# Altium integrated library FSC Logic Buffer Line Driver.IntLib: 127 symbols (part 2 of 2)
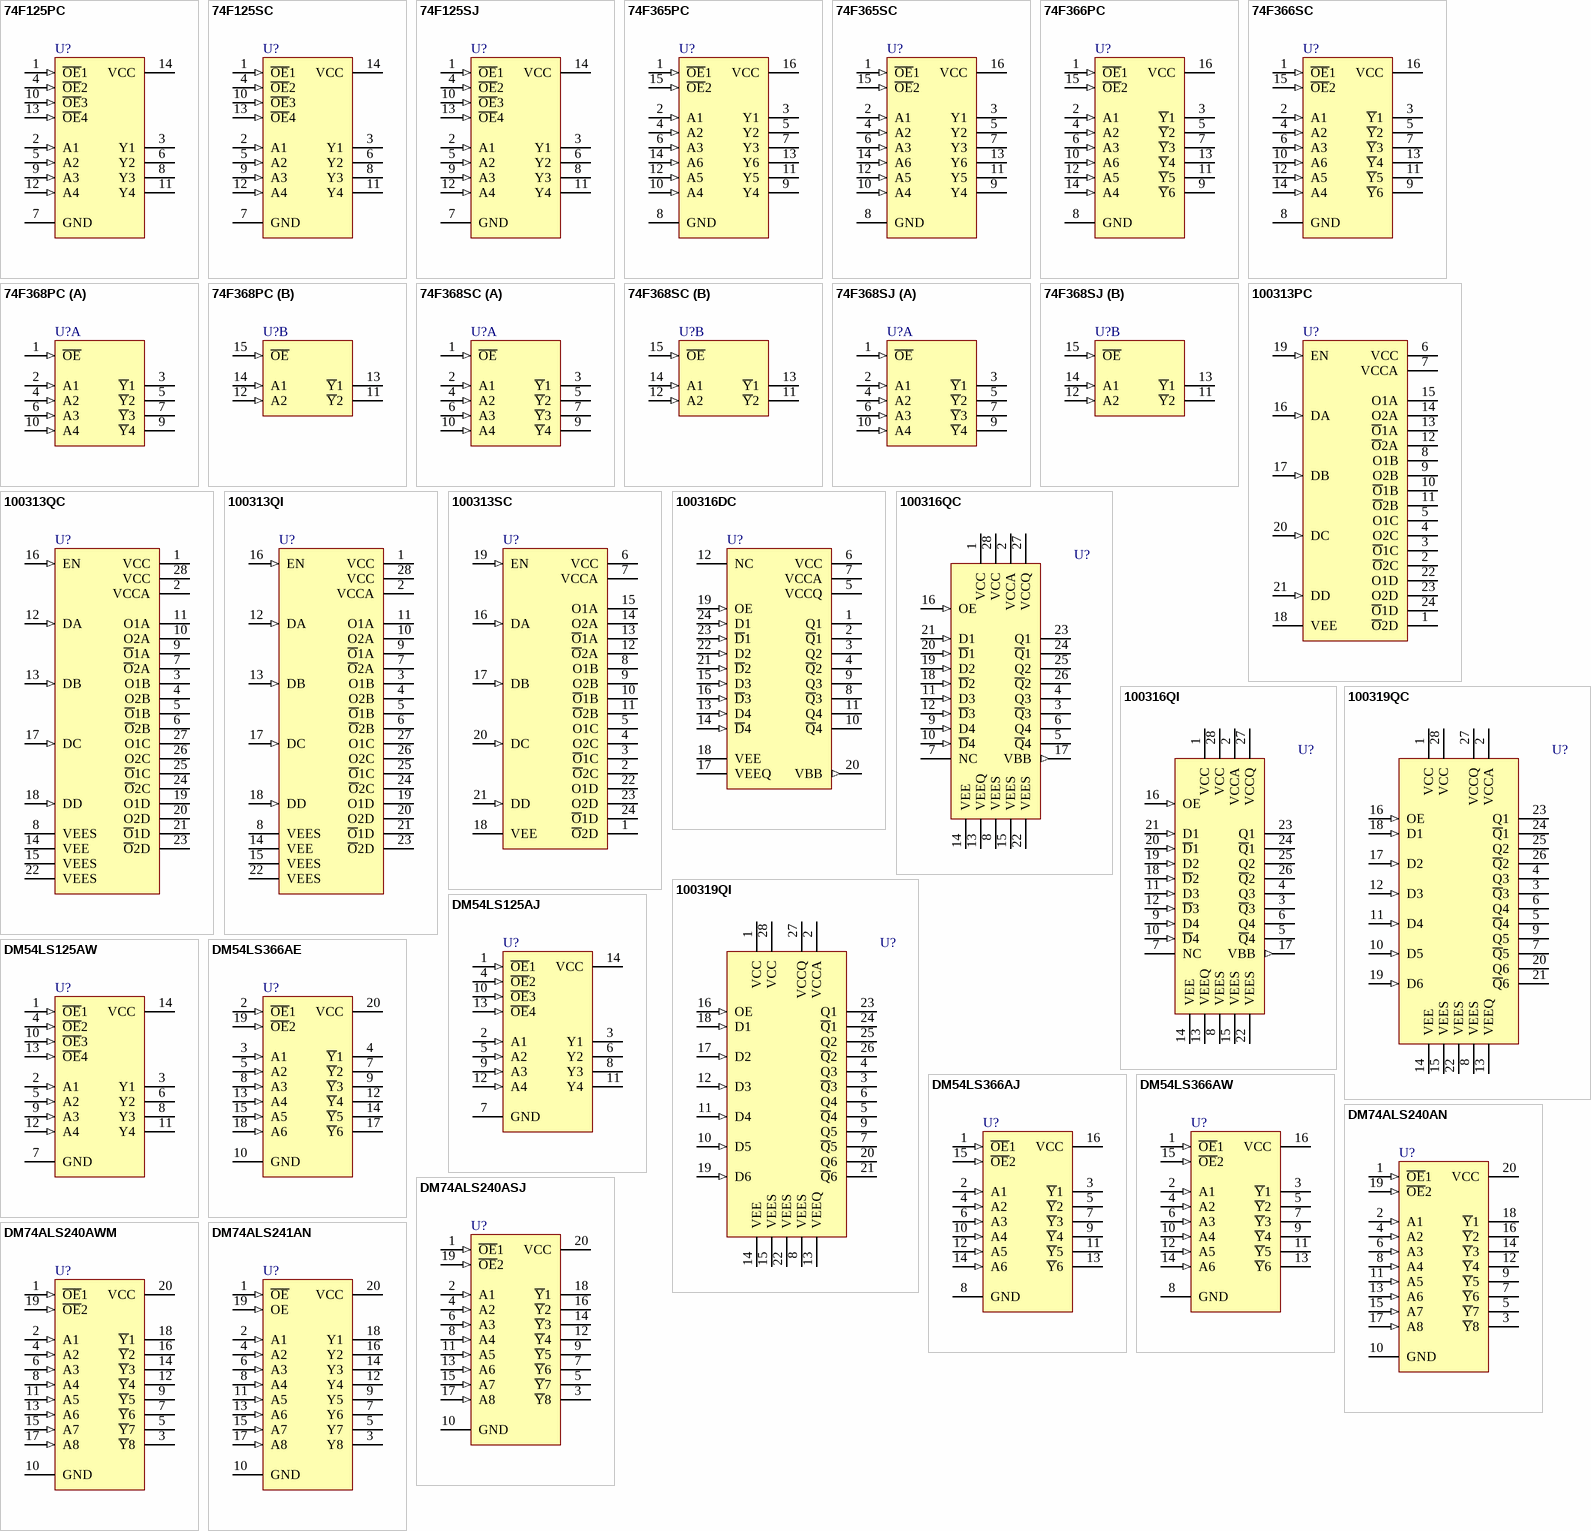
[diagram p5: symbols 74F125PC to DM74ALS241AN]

## 100313PC
designator U?
Low Power Quad Driver; Note: All inputs have 50k Ohm pull-down resistors. VCC = VCCA = GND.
footprint N24E (DIP, 24-Leads, Row Spacing 10.16mm, Pitch 2.54mm, Body 30.59x8.69mm)
3D model 6Y (DIP, 24-Pin, Row Spacing 10.16 mm, Pitch 2.54 mm)
pins: 1 ~{O}2D (oe), 2 ~{O}2C (oe), 3 ~{O}1C (oe), 4 O2C (oe), 5 O1C (oe), 6 VCC (power), 7 VCCA (power), 8 O1B (oe), 9 O2B (oe), 10 ~{O}1B (oe), 11 ~{O}2B (oe), 12 ~{O}2A (oe), 13 ~{O}1A (oe), 14 O2A (oe), 15 O1A (oe), 16 DA (in), 17 DB (in), 18 VEE (power), 19 EN (in), 20 DC (in), 21 DD (in), 22 O1D (oe), 23 O2D (oe), 24 ~{O}1D (oe)

## 100313QC
designator U?
Low Power Quad Driver; Note: All inputs have 50k Ohm pull-down resistors. VCC = VCCA = GND.
footprint V28A_N (Leaded Chip Carrier, 28-Leads, Body 11.5x11.5mm, Pitch 1.27mm, IPC Medium Density)
footprint V28A_L (Leaded Chip Carrier, 28-Leads, Body 11.5x11.5mm, Pitch 1.27mm, IPC High Density)
footprint V28A_M (Leaded Chip Carrier, 28-Leads, Body 11.5x11.5mm, Pitch 1.27mm, IPC Low Density)
3D model 100313-V28A (28-Pin Leaded Chip Carrier 1.27 mm Pitch)
pins: 1 VCC (power), 2 VCCA (power), 3 O1B (oe), 4 O2B (oe), 5 ~{O}1B (oe), 6 ~{O}2B (oe), 7 ~{O}2A (oe), 8 VEES (power), 9 ~{O}1A (oe), 10 O2A (oe), 11 O1A (oe), 12 DA (in), 13 DB (in), 14 VEE (power), 15 VEES (power), 16 EN (in), 17 DC (in), 18 DD (in), 19 O1D (oe), 20 O2D (oe), 21 ~{O}1D (oe), 22 VEES (power), 23 ~{O}2D (oe), 24 ~{O}2C (oe), 25 ~{O}1C (oe), 26 O2C (oe), 27 O1C (oe), 28 VCC (power)

## 100313QI
designator U?
Low Power Quad Driver; Note: All inputs have 50k Ohm pull-down resistors. VCC = VCCA = GND.
footprint V28A_N (Leaded Chip Carrier, 28-Leads, Body 11.5x11.5mm, Pitch 1.27mm, IPC Medium Density)
footprint V28A_L (Leaded Chip Carrier, 28-Leads, Body 11.5x11.5mm, Pitch 1.27mm, IPC High Density)
footprint V28A_M (Leaded Chip Carrier, 28-Leads, Body 11.5x11.5mm, Pitch 1.27mm, IPC Low Density)
3D model 100313-V28A (28-Pin Leaded Chip Carrier 1.27 mm Pitch)
pins: 1 VCC (power), 2 VCCA (power), 3 O1B (oe), 4 O2B (oe), 5 ~{O}1B (oe), 6 ~{O}2B (oe), 7 ~{O}2A (oe), 8 VEES (power), 9 ~{O}1A (oe), 10 O2A (oe), 11 O1A (oe), 12 DA (in), 13 DB (in), 14 VEE (power), 15 VEES (power), 16 EN (in), 17 DC (in), 18 DD (in), 19 O1D (oe), 20 O2D (oe), 21 ~{O}1D (oe), 22 VEES (power), 23 ~{O}2D (oe), 24 ~{O}2C (oe), 25 ~{O}1C (oe), 26 O2C (oe), 27 O1C (oe), 28 VCC (power)

## 100313SC
designator U?
Low Power Quad Driver; Note: All inputs have 50k Ohm pull-down resistors. VCC = VCCA = GND.
footprint M24B_N (SOIC, 24-Leads, Body 15.4x7.5mm, Pitch 1.27mm, IPC Medium Density)
footprint M24B_L (SOIC, 24-Leads, Body 15.4x7.5mm, Pitch 1.27mm, IPC High Density)
footprint M24B_M (SOIC, 24-Leads, Body 15.4x7.5mm, Pitch 1.27mm, IPC Low Density)
3D model M24B (24-Pin Small Outline Integrated Circuit 1.27 mm Pitch)
pins: 1 ~{O}2D (oe), 2 ~{O}2C (oe), 3 ~{O}1C (oe), 4 O2C (oe), 5 O1C (oe), 6 VCC (power), 7 VCCA (power), 8 O1B (oe), 9 O2B (oe), 10 ~{O}1B (oe), 11 ~{O}2B (oe), 12 ~{O}2A (oe), 13 ~{O}1A (oe), 14 O2A (oe), 15 O1A (oe), 16 DA (in), 17 DB (in), 18 VEE (power), 19 EN (in), 20 DC (in), 21 DD (in), 22 O1D (oe), 23 O2D (oe), 24 ~{O}1D (oe)

## 100316DC
designator U?
Low Power Quad Differential Line Driver with Cut-Off; Note: VCC = VCCA = GND.
footprint J24E (DIP, 24-Leads, Row Spacing 10.16mm, Pitch 2.54mm, Body 30.48x9.14mm)
3D model 6Y (DIP, 24-Pin, Row Spacing 10.16 mm, Pitch 2.54 mm)
pins: 1 Q1 (hiz), 2 ~{Q}1 (hiz), 3 Q2 (hiz), 4 ~{Q}2 (hiz), 5 VCCQ (power), 6 VCC (power), 7 VCCA (power), 8 ~{Q}3 (hiz), 9 Q3 (hiz), 10 ~{Q}4 (hiz), 11 Q4 (hiz), 12 NC, 13 D4 (in), 14 ~{D}4 (in), 15 D3 (in), 16 ~{D}3 (in), 17 VEEQ (power), 18 VEE (power), 19 OE (in), 20 VBB (out), 21 ~{D}2 (in), 22 D2 (in), 23 ~{D}1 (in), 24 D1 (in)

## 100316QC
designator U?
Low Power Quad Differential Line Driver with Cut-Off; Note: VCC = VCCA = GND.
footprint V28A_N (Leaded Chip Carrier, 28-Leads, Body 11.5x11.5mm, Pitch 1.27mm, IPC Medium Density)
footprint V28A_L (Leaded Chip Carrier, 28-Leads, Body 11.5x11.5mm, Pitch 1.27mm, IPC High Density)
footprint V28A_M (Leaded Chip Carrier, 28-Leads, Body 11.5x11.5mm, Pitch 1.27mm, IPC Low Density)
3D model 100316-V28A (28-Pin Leaded Chip Carrier 1.27 mm Pitch)
pins: 1 VCC (power), 2 VCCA (power), 3 ~{Q}3 (hiz), 4 Q3 (hiz), 5 ~{Q}4 (hiz), 6 Q4 (hiz), 7 NC, 8 VEES (power), 9 D4 (in), 10 ~{D}4 (in), 11 D3 (in), 12 ~{D}3 (in), 13 VEEQ (power), 14 VEE (power), 15 VEES (power), 16 OE (in), 17 VBB (out), 18 ~{D}2 (in), 19 D2 (in), 20 ~{D}1 (in), 21 D1 (in), 22 VEES (power), 23 Q1 (hiz), 24 ~{Q}1 (hiz), 25 Q2 (hiz), 26 ~{Q}2 (hiz), 27 VCCQ (power), 28 VCC (power)

## 100316QI
designator U?
Low Power Quad Differential Line Driver with Cut-Off; Note: VCC = VCCA = GND.
footprint V28A_N (Leaded Chip Carrier, 28-Leads, Body 11.5x11.5mm, Pitch 1.27mm, IPC Medium Density)
footprint V28A_L (Leaded Chip Carrier, 28-Leads, Body 11.5x11.5mm, Pitch 1.27mm, IPC High Density)
footprint V28A_M (Leaded Chip Carrier, 28-Leads, Body 11.5x11.5mm, Pitch 1.27mm, IPC Low Density)
3D model 100316-V28A (28-Pin Leaded Chip Carrier 1.27 mm Pitch)
pins: 1 VCC (power), 2 VCCA (power), 3 ~{Q}3 (hiz), 4 Q3 (hiz), 5 ~{Q}4 (hiz), 6 Q4 (hiz), 7 NC, 8 VEES (power), 9 D4 (in), 10 ~{D}4 (in), 11 D3 (in), 12 ~{D}3 (in), 13 VEEQ (power), 14 VEE (power), 15 VEES (power), 16 OE (in), 17 VBB (out), 18 ~{D}2 (in), 19 D2 (in), 20 ~{D}1 (in), 21 D1 (in), 22 VEES (power), 23 Q1 (hiz), 24 ~{Q}1 (hiz), 25 Q2 (hiz), 26 ~{Q}2 (hiz), 27 VCCQ (power), 28 VCC (power)

## 100319QC
designator U?
Low Power Hex Line Driver with Cut-Off; Note: VCC = VCCA = GND.
footprint V28A_N (Leaded Chip Carrier, 28-Leads, Body 11.5x11.5mm, Pitch 1.27mm, IPC Medium Density)
footprint V28A_L (Leaded Chip Carrier, 28-Leads, Body 11.5x11.5mm, Pitch 1.27mm, IPC High Density)
footprint V28A_M (Leaded Chip Carrier, 28-Leads, Body 11.5x11.5mm, Pitch 1.27mm, IPC Low Density)
3D model 100319-V28A (28-Pin Leaded Chip Carrier 1.27 mm Pitch)
pins: 1 VCC (power), 2 VCCA (power), 3 ~{Q}3 (oe), 4 Q3 (oe), 5 ~{Q}4 (oe), 6 Q4 (oe), 7 ~{Q}5 (oe), 8 VEES (power), 9 Q5 (oe), 10 D5 (in), 11 D4 (in), 12 D3 (in), 13 VEEQ (power), 14 VEE (power), 15 VEES (power), 16 OE (in), 17 D2 (in), 18 D1 (in), 19 D6 (in), 20 Q6 (oe), 21 ~{Q}6 (oe), 22 VEES (power), 23 Q1 (hiz), 24 ~{Q}1 (hiz), 25 Q2 (hiz), 26 ~{Q}2 (hiz), 27 VCCQ (power), 28 VCC (power)

## 100319QI
designator U?
Low Power Hex Line Driver with Cut-Off; Note: VCC = VCCA = GND.
footprint V28A_N (Leaded Chip Carrier, 28-Leads, Body 11.5x11.5mm, Pitch 1.27mm, IPC Medium Density)
footprint V28A_L (Leaded Chip Carrier, 28-Leads, Body 11.5x11.5mm, Pitch 1.27mm, IPC High Density)
footprint V28A_M (Leaded Chip Carrier, 28-Leads, Body 11.5x11.5mm, Pitch 1.27mm, IPC Low Density)
3D model 100319-V28A (28-Pin Leaded Chip Carrier 1.27 mm Pitch)
pins: 1 VCC (power), 2 VCCA (power), 3 ~{Q}3 (oe), 4 Q3 (oe), 5 ~{Q}4 (oe), 6 Q4 (oe), 7 ~{Q}5 (oe), 8 VEES (power), 9 Q5 (oe), 10 D5 (in), 11 D4 (in), 12 D3 (in), 13 VEEQ (power), 14 VEE (power), 15 VEES (power), 16 OE (in), 17 D2 (in), 18 D1 (in), 19 D6 (in), 20 Q6 (oe), 21 ~{Q}6 (oe), 22 VEES (power), 23 Q1 (hiz), 24 ~{Q}1 (hiz), 25 Q2 (hiz), 26 ~{Q}2 (hiz), 27 VCCQ (power), 28 VCC (power)

## DM54LS125AJ
designator U?
Quad 3-State Buffer
footprint J14A (DIP, 14-Leads, Row Spacing 7.62mm, Pitch 2.54mm, Body 19.56x6.73mm)
3D model J14A (CerDIP, 14-Pin, Row Spacing 7.62 mm, Pitch 2.54 mm)
simulation model 74LS125 (SIMCODE)
signal-integrity model DM54LS125AJ
pins: 1 ~{OE}1 (in), 2 A1 (in), 3 Y1 (hiz), 4 ~{OE}2 (in), 5 A2 (in), 6 Y2 (hiz), 7 GND (power), 8 Y3 (hiz), 9 A3 (in), 10 ~{OE}3 (in), 11 Y4 (hiz), 12 A4 (in), 13 ~{OE}4 (in), 14 VCC (power)

## DM54LS125AW
designator U?
Quad 3-State Buffer
footprint W14B (DFP; 14 Leads; Body 9.8 x 7.1 mm (LxW max); Pitch 1.27 mm)
3D model W14B (DFP; 14 Leads; Body 9.8 x 7.1 mm (LxW max); Pitch 1.27 mm)
simulation model 74LS125 (SIMCODE)
signal-integrity model DM54LS125AW
pins: 1 ~{OE}1 (in), 2 A1 (in), 3 Y1 (hiz), 4 ~{OE}2 (in), 5 A2 (in), 6 Y2 (hiz), 7 GND (power), 8 Y3 (hiz), 9 A3 (in), 10 ~{OE}3 (in), 11 Y4 (hiz), 12 A4 (in), 13 ~{OE}4 (in), 14 VCC (power)

## DM54LS366AE
designator U?
Hex 3-State Inverting Buffer; Note: Pins 1, 6, 11 and 16 are not connected and not drawn.
footprint E20A (Leadless Chip Carrier; 20 Terminals; Body 8.9 x 8.9 mm)
footprint E20A_N (Leadless Chip Carrier, 20-Leads, Body 8.9x8.9mm, Pitch 1.27mm, IPC Medium Density)
footprint E20A_L (Leadless Chip Carrier, 20-Leads, Body 8.9x8.9mm, Pitch 1.27mm, IPC High Density)
footprint E20A_M (Leadless Chip Carrier, 20-Leads, Body 8.9x8.9mm, Pitch 1.27mm, IPC Low Density)
signal-integrity model DM54LS366AE
pins: 2 ~{OE}1 (in), 3 A1 (in), 4 ~{Y}1 (hiz), 5 A2 (in), 7 ~{Y}2 (hiz), 8 A3 (in), 9 ~{Y}3 (hiz), 10 GND (power), 12 ~{Y}4 (hiz), 13 A4 (in), 14 ~{Y}5 (hiz), 15 A5 (in), 17 ~{Y}6 (hiz), 18 A6 (in), 19 ~{OE}2 (in), 20 VCC (power)

## DM54LS366AJ
designator U?
Hex 3-State Inverting Buffer
footprint J16A (DIP, 16-Leads, Row Spacing 7.62mm, Pitch 2.54mm, Body 19.56x6.73mm)
3D model N16E (CerDIP, 16-Pin, Row Spacing 7.62 mm, Pitch 2.54 mm)
signal-integrity model DM54LS366AJ
pins: 1 ~{OE}1 (in), 2 A1 (in), 3 ~{Y}1 (hiz), 4 A2 (in), 5 ~{Y}2 (hiz), 6 A3 (in), 7 ~{Y}3 (hiz), 8 GND (power), 9 ~{Y}4 (hiz), 10 A4 (in), 11 ~{Y}5 (hiz), 12 A5 (in), 13 ~{Y}6 (hiz), 14 A6 (in), 15 ~{OE}2 (in), 16 VCC (power)

## DM54LS366AW
designator U?
Hex 3-State Inverting Buffer
footprint W16A (DFP; 16 Leads; Body 9.9 x 7.6 mm (LxW max); Pitch 1.27 mm)
3D model W16A (DFP; 16 Leads; Body 9.9 x 7.6 mm (LxW max); Pitch 1.27 mm)
signal-integrity model DM54LS366AW
pins: 1 ~{OE}1 (in), 2 A1 (in), 3 ~{Y}1 (hiz), 4 A2 (in), 5 ~{Y}2 (hiz), 6 A3 (in), 7 ~{Y}3 (hiz), 8 GND (power), 9 ~{Y}4 (hiz), 10 A4 (in), 11 ~{Y}5 (hiz), 12 A5 (in), 13 ~{Y}6 (hiz), 14 A6 (in), 15 ~{OE}2 (in), 16 VCC (power)

## DM74ALS240AN
designator U?
Octal 3-State Bus Driver
footprint N20A (DIP, 20-Leads, Row Spacing 7.62mm, Pitch 2.54mm, Body 26.07x6.6mm)
3D model N20A (DIP, 20-Pin, Row Spacing 7.62 mm, Pitch 2.54 mm)
simulation model 74LS240 (SIMCODE)
signal-integrity model DM74ALS240AN
pins: 1 ~{OE}1 (in), 2 A1 (in), 3 ~{Y}8 (hiz), 4 A2 (in), 5 ~{Y}7 (hiz), 6 A3 (in), 7 ~{Y}6 (hiz), 8 A4 (in), 9 ~{Y}5 (hiz), 10 GND (power), 11 A5 (in), 12 ~{Y}4 (hiz), 13 A6 (in), 14 ~{Y}3 (hiz), 15 A7 (in), 16 ~{Y}2 (hiz), 17 A8 (in), 18 ~{Y}1 (hiz), 19 ~{OE}2 (in), 20 VCC (power)

## DM74ALS240ASJ
designator U?
Octal 3-State Bus Driver
footprint M20D_N (SOP, 20-Leads, Body 12.6x5.3mm, Pitch 1.27mm, IPC Medium Density)
footprint M20D_L (SOP, 20-Leads, Body 12.6x5.3mm, Pitch 1.27mm, IPC High Density)
footprint M20D_M (SOP, 20-Leads, Body 12.6x5.3mm, Pitch 1.27mm, IPC Low Density)
3D model M20D (20-Pin Small Outline Package 1.27 mm Pitch)
simulation model 74LS240 (SIMCODE)
signal-integrity model DM74ALS240ASJ
pins: 1 ~{OE}1 (in), 2 A1 (in), 3 ~{Y}8 (hiz), 4 A2 (in), 5 ~{Y}7 (hiz), 6 A3 (in), 7 ~{Y}6 (hiz), 8 A4 (in), 9 ~{Y}5 (hiz), 10 GND (power), 11 A5 (in), 12 ~{Y}4 (hiz), 13 A6 (in), 14 ~{Y}3 (hiz), 15 A7 (in), 16 ~{Y}2 (hiz), 17 A8 (in), 18 ~{Y}1 (hiz), 19 ~{OE}2 (in), 20 VCC (power)

## DM74ALS240AWM
designator U?
Octal 3-State Bus Driver
footprint M20B_N (SOIC, 20-Leads, Body 12.8x7.5mm, Pitch 1.27mm, IPC Medium Density)
footprint M20B_L (SOIC, 20-Leads, Body 12.8x7.5mm, Pitch 1.27mm, IPC High Density)
footprint M20B_M (SOIC, 20-Leads, Body 12.8x7.5mm, Pitch 1.27mm, IPC Low Density)
3D model M20B (20-Pin Small Outline Integrated Circuit 1.27 mm Pitch)
simulation model 74LS240 (SIMCODE)
signal-integrity model DM74ALS240AWM
pins: 1 ~{OE}1 (in), 2 A1 (in), 3 ~{Y}8 (hiz), 4 A2 (in), 5 ~{Y}7 (hiz), 6 A3 (in), 7 ~{Y}6 (hiz), 8 A4 (in), 9 ~{Y}5 (hiz), 10 GND (power), 11 A5 (in), 12 ~{Y}4 (hiz), 13 A6 (in), 14 ~{Y}3 (hiz), 15 A7 (in), 16 ~{Y}2 (hiz), 17 A8 (in), 18 ~{Y}1 (hiz), 19 ~{OE}2 (in), 20 VCC (power)

## DM74ALS241AN
designator U?
Octal 3-State Bus Driver
footprint N20A (DIP, 20-Leads, Row Spacing 7.62mm, Pitch 2.54mm, Body 26.07x6.6mm)
3D model N20A (DIP, 20-Pin, Row Spacing 7.62 mm, Pitch 2.54 mm)
simulation model 74LS241 (SIMCODE)
signal-integrity model DM74ALS241AN
pins: 1 ~{OE} (in), 2 A1 (in), 3 Y8 (hiz), 4 A2 (in), 5 Y7 (hiz), 6 A3 (in), 7 Y6 (hiz), 8 A4 (in), 9 Y5 (hiz), 10 GND (power), 11 A5 (in), 12 Y4 (hiz), 13 A6 (in), 14 Y3 (hiz), 15 A7 (in), 16 Y2 (hiz), 17 A8 (in), 18 Y1 (hiz), 19 OE (in), 20 VCC (power)

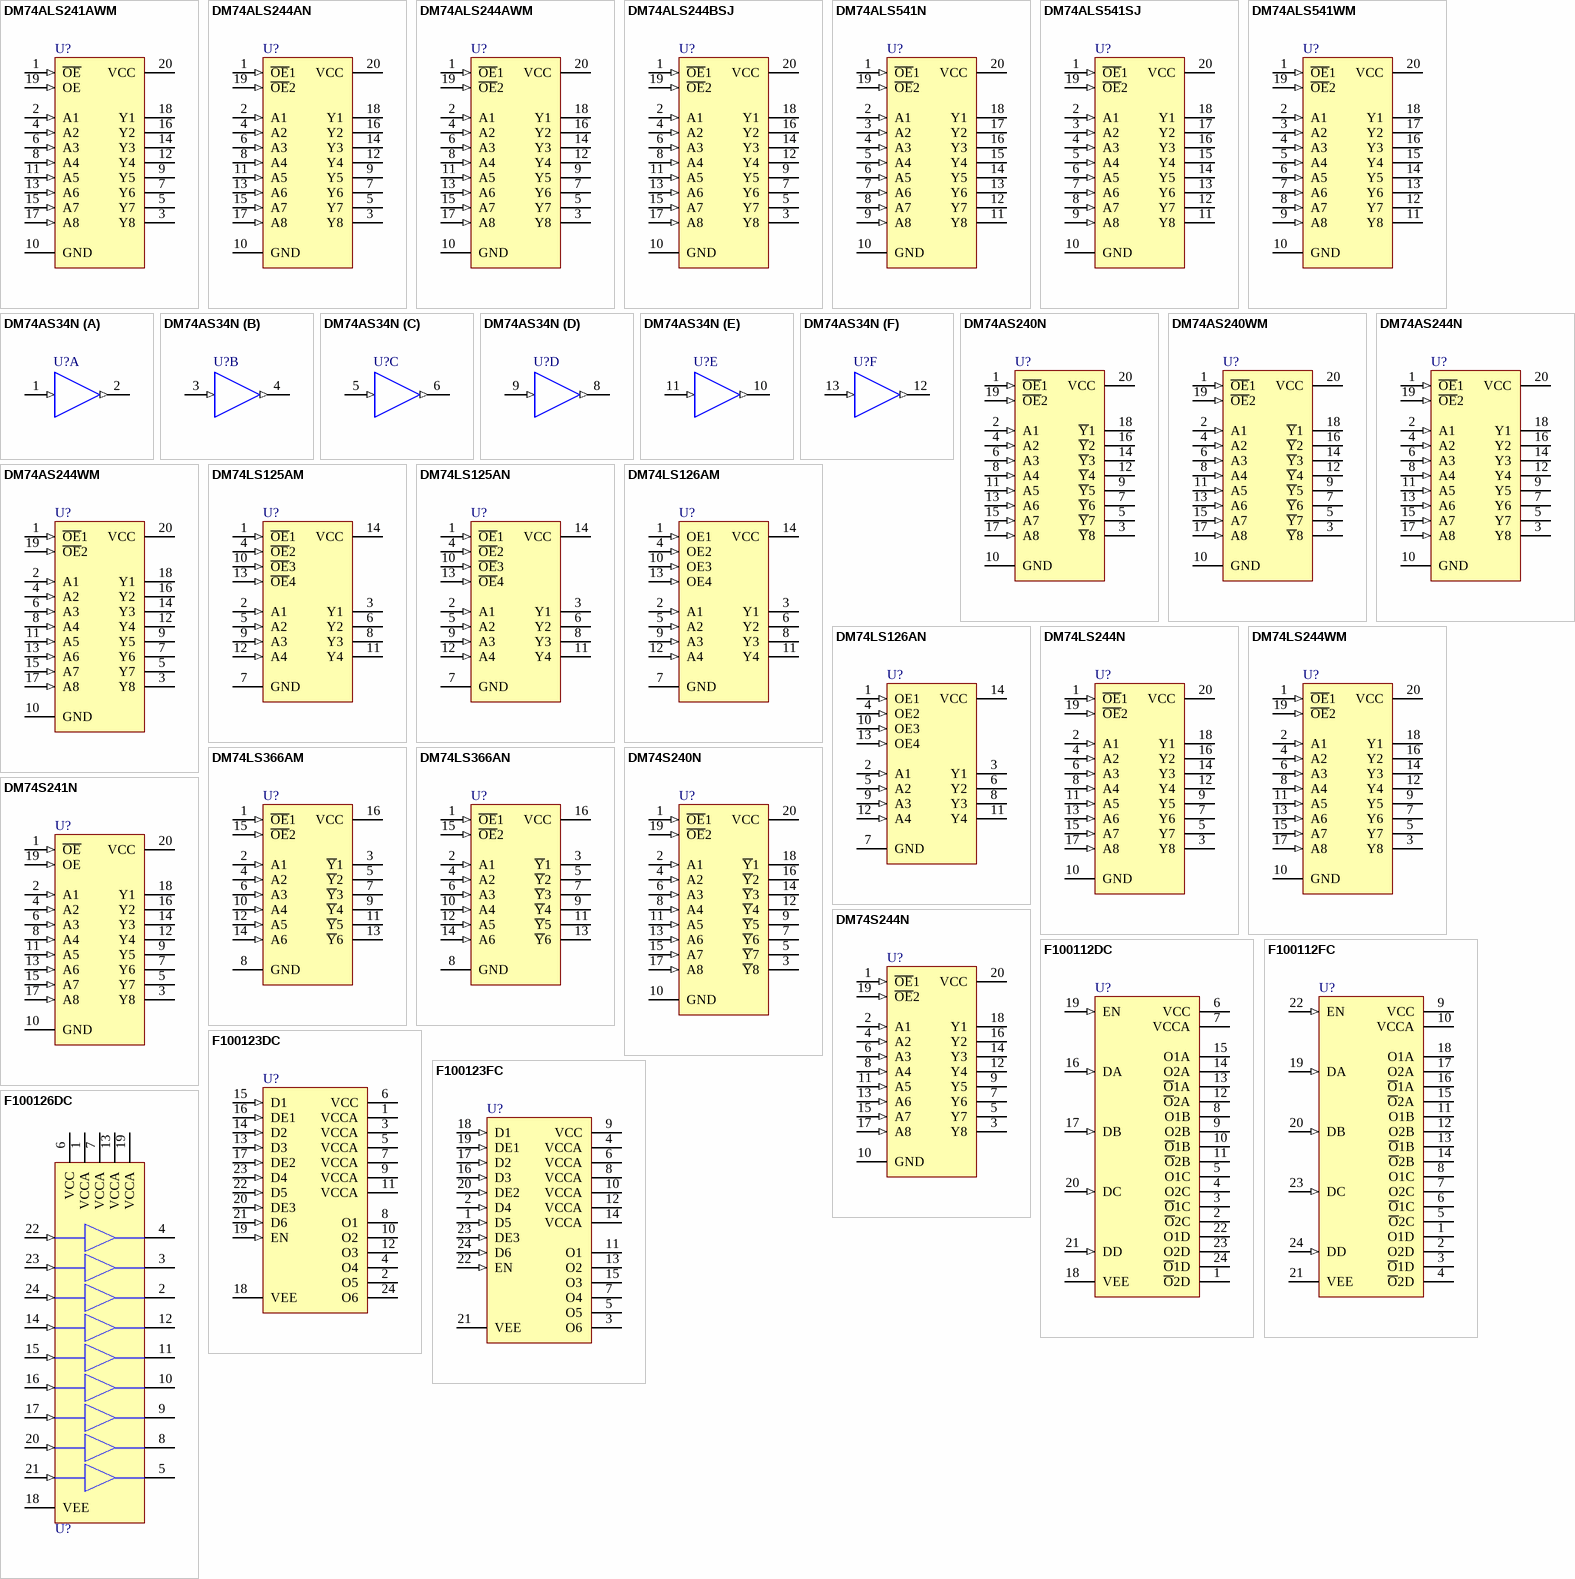
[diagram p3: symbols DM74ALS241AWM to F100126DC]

## DM74ALS241AWM
designator U?
Octal 3-State Bus Driver
footprint M20B_N (SOIC, 20-Leads, Body 12.8x7.5mm, Pitch 1.27mm, IPC Medium Density)
footprint M20B_L (SOIC, 20-Leads, Body 12.8x7.5mm, Pitch 1.27mm, IPC High Density)
footprint M20B_M (SOIC, 20-Leads, Body 12.8x7.5mm, Pitch 1.27mm, IPC Low Density)
3D model M20B (20-Pin Small Outline Integrated Circuit 1.27 mm Pitch)
simulation model 74LS241 (SIMCODE)
signal-integrity model DM74ALS241AWM
pins: 1 ~{OE} (in), 2 A1 (in), 3 Y8 (hiz), 4 A2 (in), 5 Y7 (hiz), 6 A3 (in), 7 Y6 (hiz), 8 A4 (in), 9 Y5 (hiz), 10 GND (power), 11 A5 (in), 12 Y4 (hiz), 13 A6 (in), 14 Y3 (hiz), 15 A7 (in), 16 Y2 (hiz), 17 A8 (in), 18 Y1 (hiz), 19 OE (in), 20 VCC (power)

## DM74ALS244AN
designator U?
Octal 3-State Bus Driver
footprint N20A (DIP, 20-Leads, Row Spacing 7.62mm, Pitch 2.54mm, Body 26.07x6.6mm)
3D model N20A (DIP, 20-Pin, Row Spacing 7.62 mm, Pitch 2.54 mm)
simulation model 74LS244 (SIMCODE)
signal-integrity model DM74ALS244AN
pins: 1 ~{OE}1 (in), 2 A1 (in), 3 Y8 (hiz), 4 A2 (in), 5 Y7 (hiz), 6 A3 (in), 7 Y6 (hiz), 8 A4 (in), 9 Y5 (hiz), 10 GND (power), 11 A5 (in), 12 Y4 (hiz), 13 A6 (in), 14 Y3 (hiz), 15 A7 (in), 16 Y2 (hiz), 17 A8 (in), 18 Y1 (hiz), 19 ~{OE}2 (in), 20 VCC (power)

## DM74ALS244AWM
designator U?
Octal 3-State Bus Driver
footprint M20B_N (SOIC, 20-Leads, Body 12.8x7.5mm, Pitch 1.27mm, IPC Medium Density)
footprint M20B_L (SOIC, 20-Leads, Body 12.8x7.5mm, Pitch 1.27mm, IPC High Density)
footprint M20B_M (SOIC, 20-Leads, Body 12.8x7.5mm, Pitch 1.27mm, IPC Low Density)
3D model M20B (20-Pin Small Outline Integrated Circuit 1.27 mm Pitch)
simulation model 74LS244 (SIMCODE)
signal-integrity model DM74ALS244AWM
pins: 1 ~{OE}1 (in), 2 A1 (in), 3 Y8 (hiz), 4 A2 (in), 5 Y7 (hiz), 6 A3 (in), 7 Y6 (hiz), 8 A4 (in), 9 Y5 (hiz), 10 GND (power), 11 A5 (in), 12 Y4 (hiz), 13 A6 (in), 14 Y3 (hiz), 15 A7 (in), 16 Y2 (hiz), 17 A8 (in), 18 Y1 (hiz), 19 ~{OE}2 (in), 20 VCC (power)

## DM74ALS244BSJ
designator U?
Octal 3-State Bus Driver
footprint M20D_N (SOP, 20-Leads, Body 12.6x5.3mm, Pitch 1.27mm, IPC Medium Density)
footprint M20D_L (SOP, 20-Leads, Body 12.6x5.3mm, Pitch 1.27mm, IPC High Density)
footprint M20D_M (SOP, 20-Leads, Body 12.6x5.3mm, Pitch 1.27mm, IPC Low Density)
3D model M20D (20-Pin Small Outline Package 1.27 mm Pitch)
simulation model 74LS244 (SIMCODE)
signal-integrity model DM74ALS244BSJ
pins: 1 ~{OE}1 (in), 2 A1 (in), 3 Y8 (hiz), 4 A2 (in), 5 Y7 (hiz), 6 A3 (in), 7 Y6 (hiz), 8 A4 (in), 9 Y5 (hiz), 10 GND (power), 11 A5 (in), 12 Y4 (hiz), 13 A6 (in), 14 Y3 (hiz), 15 A7 (in), 16 Y2 (hiz), 17 A8 (in), 18 Y1 (hiz), 19 ~{OE}2 (in), 20 VCC (power)

## DM74ALS541N
designator U?
Octal Buffer and Line Driver with 3-State Output
footprint N20A (DIP, 20-Leads, Row Spacing 7.62mm, Pitch 2.54mm, Body 26.07x6.6mm)
3D model N20A (DIP, 20-Pin, Row Spacing 7.62 mm, Pitch 2.54 mm)
signal-integrity model DM74ALS541N
pins: 1 ~{OE}1 (in), 2 A1 (in), 3 A2 (in), 4 A3 (in), 5 A4 (in), 6 A5 (in), 7 A6 (in), 8 A7 (in), 9 A8 (in), 10 GND (power), 11 Y8 (hiz), 12 Y7 (hiz), 13 Y6 (hiz), 14 Y5 (hiz), 15 Y4 (hiz), 16 Y3 (hiz), 17 Y2 (hiz), 18 Y1 (hiz), 19 ~{OE}2 (in), 20 VCC (power)

## DM74ALS541SJ
designator U?
Octal Buffer and Line Driver with 3-State Output
footprint M20D_N (SOP, 20-Leads, Body 12.6x5.3mm, Pitch 1.27mm, IPC Medium Density)
footprint M20D_L (SOP, 20-Leads, Body 12.6x5.3mm, Pitch 1.27mm, IPC High Density)
footprint M20D_M (SOP, 20-Leads, Body 12.6x5.3mm, Pitch 1.27mm, IPC Low Density)
3D model M20D (20-Pin Small Outline Package 1.27 mm Pitch)
signal-integrity model DM74ALS541SJ
pins: 1 ~{OE}1 (in), 2 A1 (in), 3 A2 (in), 4 A3 (in), 5 A4 (in), 6 A5 (in), 7 A6 (in), 8 A7 (in), 9 A8 (in), 10 GND (power), 11 Y8 (hiz), 12 Y7 (hiz), 13 Y6 (hiz), 14 Y5 (hiz), 15 Y4 (hiz), 16 Y3 (hiz), 17 Y2 (hiz), 18 Y1 (hiz), 19 ~{OE}2 (in), 20 VCC (power)

## DM74ALS541WM
designator U?
Octal Buffer and Line Driver with 3-State Output
footprint M20B_N (SOIC, 20-Leads, Body 12.8x7.5mm, Pitch 1.27mm, IPC Medium Density)
footprint M20B_L (SOIC, 20-Leads, Body 12.8x7.5mm, Pitch 1.27mm, IPC High Density)
footprint M20B_M (SOIC, 20-Leads, Body 12.8x7.5mm, Pitch 1.27mm, IPC Low Density)
3D model M20B (20-Pin Small Outline Integrated Circuit 1.27 mm Pitch)
signal-integrity model DM74ALS541WM
pins: 1 ~{OE}1 (in), 2 A1 (in), 3 A2 (in), 4 A3 (in), 5 A4 (in), 6 A5 (in), 7 A6 (in), 8 A7 (in), 9 A8 (in), 10 GND (power), 11 Y8 (hiz), 12 Y7 (hiz), 13 Y6 (hiz), 14 Y5 (hiz), 15 Y4 (hiz), 16 Y3 (hiz), 17 Y2 (hiz), 18 Y1 (hiz), 19 ~{OE}2 (in), 20 VCC (power)

## DM74AS34N
designator U?
Hex Non-Inverter
footprint N14A (DIP, 14-Leads, Row Spacing 7.62mm, Pitch 2.54mm, Body 19.18x6.35mm)
3D model N14A (DIP, 14-Pin, Row Spacing 7.62 mm, Pitch 2.54 mm)
signal-integrity model DM74AS34N
pins on every part: 7 GND (power) hidden to GND, 14 VCC (power) hidden to VCC
part A pins: 1 A (in), 2 Y (out)
part B pins: 3 A (in), 4 Y (out)
part C pins: 5 A (in), 6 Y (out)
part D pins: 8 Y (out), 9 A (in)
part E pins: 10 Y (out), 11 A (in)
part F pins: 12 Y (out), 13 A (in)

## DM74AS240N
designator U?
3-State Bus Driver/Receiver
footprint N20A (DIP, 20-Leads, Row Spacing 7.62mm, Pitch 2.54mm, Body 26.07x6.6mm)
3D model N20A (DIP, 20-Pin, Row Spacing 7.62 mm, Pitch 2.54 mm)
signal-integrity model DM74AS240N
pins: 1 ~{OE}1 (in), 2 A1 (in), 3 ~{Y}8 (hiz), 4 A2 (in), 5 ~{Y}7 (hiz), 6 A3 (in), 7 ~{Y}6 (hiz), 8 A4 (in), 9 ~{Y}5 (hiz), 10 GND (power), 11 A5 (in), 12 ~{Y}4 (hiz), 13 A6 (in), 14 ~{Y}3 (hiz), 15 A7 (in), 16 ~{Y}2 (hiz), 17 A8 (in), 18 ~{Y}1 (hiz), 19 ~{OE}2 (in), 20 VCC (power)

## DM74AS240WM
designator U?
3-State Bus Driver/Receiver
footprint M20B_N (SOIC, 20-Leads, Body 12.8x7.5mm, Pitch 1.27mm, IPC Medium Density)
footprint M20B_L (SOIC, 20-Leads, Body 12.8x7.5mm, Pitch 1.27mm, IPC High Density)
footprint M20B_M (SOIC, 20-Leads, Body 12.8x7.5mm, Pitch 1.27mm, IPC Low Density)
3D model M20B (20-Pin Small Outline Integrated Circuit 1.27 mm Pitch)
signal-integrity model DM74AS240WM
pins: 1 ~{OE}1 (in), 2 A1 (in), 3 ~{Y}8 (hiz), 4 A2 (in), 5 ~{Y}7 (hiz), 6 A3 (in), 7 ~{Y}6 (hiz), 8 A4 (in), 9 ~{Y}5 (hiz), 10 GND (power), 11 A5 (in), 12 ~{Y}4 (hiz), 13 A6 (in), 14 ~{Y}3 (hiz), 15 A7 (in), 16 ~{Y}2 (hiz), 17 A8 (in), 18 ~{Y}1 (hiz), 19 ~{OE}2 (in), 20 VCC (power)

## DM74AS244N
designator U?
3-State Bus Driver/Receiver
footprint N20A (DIP, 20-Leads, Row Spacing 7.62mm, Pitch 2.54mm, Body 26.07x6.6mm)
3D model N20A (DIP, 20-Pin, Row Spacing 7.62 mm, Pitch 2.54 mm)
signal-integrity model DM74AS244N
pins: 1 ~{OE}1 (in), 2 A1 (in), 3 Y8 (hiz), 4 A2 (in), 5 Y7 (hiz), 6 A3 (in), 7 Y6 (hiz), 8 A4 (in), 9 Y5 (hiz), 10 GND (power), 11 A5 (in), 12 Y4 (hiz), 13 A6 (in), 14 Y3 (hiz), 15 A7 (in), 16 Y2 (hiz), 17 A8 (in), 18 Y1 (hiz), 19 ~{OE}2 (in), 20 VCC (power)

## DM74AS244WM
designator U?
3-State Bus Driver/Receiver
footprint M20B_N (SOIC, 20-Leads, Body 12.8x7.5mm, Pitch 1.27mm, IPC Medium Density)
footprint M20B_L (SOIC, 20-Leads, Body 12.8x7.5mm, Pitch 1.27mm, IPC High Density)
footprint M20B_M (SOIC, 20-Leads, Body 12.8x7.5mm, Pitch 1.27mm, IPC Low Density)
3D model M20B (20-Pin Small Outline Integrated Circuit 1.27 mm Pitch)
signal-integrity model DM74AS244WM
pins: 1 ~{OE}1 (in), 2 A1 (in), 3 Y8 (hiz), 4 A2 (in), 5 Y7 (hiz), 6 A3 (in), 7 Y6 (hiz), 8 A4 (in), 9 Y5 (hiz), 10 GND (power), 11 A5 (in), 12 Y4 (hiz), 13 A6 (in), 14 Y3 (hiz), 15 A7 (in), 16 Y2 (hiz), 17 A8 (in), 18 Y1 (hiz), 19 ~{OE}2 (in), 20 VCC (power)

## DM74LS125AM
designator U?
Quad 3-State Buffer
footprint M14A_N (SOIC, 14-Leads, Body 8.6x3.9mm, Pitch 1.27mm, IPC Medium Density)
footprint M14A_L (SOIC, 14-Leads, Body 8.6x3.9mm, Pitch 1.27mm, IPC High Density)
footprint M14A_M (SOIC, 14-Leads, Body 8.6x3.9mm, Pitch 1.27mm, IPC Low Density)
3D model M14A (14-Pin Small Outline Integrated Circuit 1.27 mm Pitch)
simulation model 74LS125 (SIMCODE)
signal-integrity model DM74LS125AM
pins: 1 ~{OE}1 (in), 2 A1 (in), 3 Y1 (hiz), 4 ~{OE}2 (in), 5 A2 (in), 6 Y2 (hiz), 7 GND (power), 8 Y3 (hiz), 9 A3 (in), 10 ~{OE}3 (in), 11 Y4 (hiz), 12 A4 (in), 13 ~{OE}4 (in), 14 VCC (power)

## DM74LS125AN
designator U?
Quad 3-State Buffer
footprint N14A (DIP, 14-Leads, Row Spacing 7.62mm, Pitch 2.54mm, Body 19.18x6.35mm)
3D model N14A (DIP, 14-Pin, Row Spacing 7.62 mm, Pitch 2.54 mm)
simulation model 74LS125 (SIMCODE)
signal-integrity model DM74LS125AN
pins: 1 ~{OE}1 (in), 2 A1 (in), 3 Y1 (hiz), 4 ~{OE}2 (in), 5 A2 (in), 6 Y2 (hiz), 7 GND (power), 8 Y3 (hiz), 9 A3 (in), 10 ~{OE}3 (in), 11 Y4 (hiz), 12 A4 (in), 13 ~{OE}4 (in), 14 VCC (power)

## DM74LS126AM
designator U?
Quad 3-State Buffer
footprint M14A_N (SOIC, 14-Leads, Body 8.6x3.9mm, Pitch 1.27mm, IPC Medium Density)
footprint M14A_L (SOIC, 14-Leads, Body 8.6x3.9mm, Pitch 1.27mm, IPC High Density)
footprint M14A_M (SOIC, 14-Leads, Body 8.6x3.9mm, Pitch 1.27mm, IPC Low Density)
3D model M14A (14-Pin Small Outline Integrated Circuit 1.27 mm Pitch)
simulation model 74LS126X4 (SIMCODE)
signal-integrity model DM74LS126AM
pins: 1 OE1 (in), 2 A1 (in), 3 Y1 (hiz), 4 OE2 (in), 5 A2 (in), 6 Y2 (hiz), 7 GND (power), 8 Y3 (hiz), 9 A3 (in), 10 OE3 (in), 11 Y4 (hiz), 12 A4 (in), 13 OE4 (in), 14 VCC (power)

## DM74LS126AN
designator U?
Quad 3-State Buffer
footprint N14A (DIP, 14-Leads, Row Spacing 7.62mm, Pitch 2.54mm, Body 19.18x6.35mm)
3D model N14A (DIP, 14-Pin, Row Spacing 7.62 mm, Pitch 2.54 mm)
simulation model 74LS126X4 (SIMCODE)
signal-integrity model DM74LS126AN
pins: 1 OE1 (in), 2 A1 (in), 3 Y1 (hiz), 4 OE2 (in), 5 A2 (in), 6 Y2 (hiz), 7 GND (power), 8 Y3 (hiz), 9 A3 (in), 10 OE3 (in), 11 Y4 (hiz), 12 A4 (in), 13 OE4 (in), 14 VCC (power)

## DM74LS244N
designator U?
Octal 3-State Buffer/Line Driver/Line Receiver
footprint N20A (DIP, 20-Leads, Row Spacing 7.62mm, Pitch 2.54mm, Body 26.07x6.6mm)
3D model N20A (DIP, 20-Pin, Row Spacing 7.62 mm, Pitch 2.54 mm)
simulation model 74LS244 (SIMCODE)
signal-integrity model DM74LS244N
pins: 1 ~{OE}1 (in), 2 A1 (in), 3 Y8 (hiz), 4 A2 (in), 5 Y7 (hiz), 6 A3 (in), 7 Y6 (hiz), 8 A4 (in), 9 Y5 (hiz), 10 GND (power), 11 A5 (in), 12 Y4 (hiz), 13 A6 (in), 14 Y3 (hiz), 15 A7 (in), 16 Y2 (hiz), 17 A8 (in), 18 Y1 (hiz), 19 ~{OE}2 (in), 20 VCC (power)

## DM74LS244WM
designator U?
Octal 3-State Buffer/Line Driver/Line Receiver
footprint M20B_N (SOIC, 20-Leads, Body 12.8x7.5mm, Pitch 1.27mm, IPC Medium Density)
footprint M20B_L (SOIC, 20-Leads, Body 12.8x7.5mm, Pitch 1.27mm, IPC High Density)
footprint M20B_M (SOIC, 20-Leads, Body 12.8x7.5mm, Pitch 1.27mm, IPC Low Density)
3D model M20B (20-Pin Small Outline Integrated Circuit 1.27 mm Pitch)
simulation model 74LS244 (SIMCODE)
signal-integrity model DM74LS244WM
pins: 1 ~{OE}1 (in), 2 A1 (in), 3 Y8 (hiz), 4 A2 (in), 5 Y7 (hiz), 6 A3 (in), 7 Y6 (hiz), 8 A4 (in), 9 Y5 (hiz), 10 GND (power), 11 A5 (in), 12 Y4 (hiz), 13 A6 (in), 14 Y3 (hiz), 15 A7 (in), 16 Y2 (hiz), 17 A8 (in), 18 Y1 (hiz), 19 ~{OE}2 (in), 20 VCC (power)

## DM74LS366AM
designator U?
Hex 3-State Inverting Buffer
footprint M16A_N (SOIC, 16-Leads, Body 9.9x3.9mm, Pitch 1.27mm, IPC Medium Density)
footprint M16A_L (SOIC, 16-Leads, Body 9.9x3.9mm, Pitch 1.27mm, IPC High Density)
footprint M16A_M (SOIC, 16-Leads, Body 9.9x3.9mm, Pitch 1.27mm, IPC Low Density)
3D model M16A (16-Pin Small Outline Integrated Circuit 1.27 mm Pitch)
signal-integrity model DM74LS366AM
pins: 1 ~{OE}1 (in), 2 A1 (in), 3 ~{Y}1 (hiz), 4 A2 (in), 5 ~{Y}2 (hiz), 6 A3 (in), 7 ~{Y}3 (hiz), 8 GND (power), 9 ~{Y}4 (hiz), 10 A4 (in), 11 ~{Y}5 (hiz), 12 A5 (in), 13 ~{Y}6 (hiz), 14 A6 (in), 15 ~{OE}2 (in), 16 VCC (power)

## DM74LS366AN
designator U?
Hex 3-State Inverting Buffer
footprint N16E (DIP, 16-Leads, Row Spacing 7.62mm, Pitch 2.54mm, Body 19.3x6.35mm)
3D model N16E (DIP, 16-Pin, Row Spacing 7.62 mm, Pitch 2.54 mm)
signal-integrity model DM74LS366AN
pins: 1 ~{OE}1 (in), 2 A1 (in), 3 ~{Y}1 (hiz), 4 A2 (in), 5 ~{Y}2 (hiz), 6 A3 (in), 7 ~{Y}3 (hiz), 8 GND (power), 9 ~{Y}4 (hiz), 10 A4 (in), 11 ~{Y}5 (hiz), 12 A5 (in), 13 ~{Y}6 (hiz), 14 A6 (in), 15 ~{OE}2 (in), 16 VCC (power)

## DM74S240N
designator U?
Octal 3-State Buffer/Line Driver/Line Receiver
footprint N20A (DIP, 20-Leads, Row Spacing 7.62mm, Pitch 2.54mm, Body 26.07x6.6mm)
3D model N20A (DIP, 20-Pin, Row Spacing 7.62 mm, Pitch 2.54 mm)
signal-integrity model DM74S240N
pins: 1 ~{OE}1 (in), 2 A1 (in), 3 ~{Y}8 (hiz), 4 A2 (in), 5 ~{Y}7 (hiz), 6 A3 (in), 7 ~{Y}6 (hiz), 8 A4 (in), 9 ~{Y}5 (hiz), 10 GND (power), 11 A5 (in), 12 ~{Y}4 (hiz), 13 A6 (in), 14 ~{Y}3 (hiz), 15 A7 (in), 16 ~{Y}2 (hiz), 17 A8 (in), 18 ~{Y}1 (hiz), 19 ~{OE}2 (in), 20 VCC (power)

## DM74S241N
designator U?
Octal 3-State Buffer/Line Driver/Line Receiver
footprint N20A (DIP, 20-Leads, Row Spacing 7.62mm, Pitch 2.54mm, Body 26.07x6.6mm)
3D model N20A (DIP, 20-Pin, Row Spacing 7.62 mm, Pitch 2.54 mm)
signal-integrity model DM74S241N
pins: 1 ~{OE} (in), 2 A1 (in), 3 Y8 (hiz), 4 A2 (in), 5 Y7 (hiz), 6 A3 (in), 7 Y6 (hiz), 8 A4 (in), 9 Y5 (hiz), 10 GND (power), 11 A5 (in), 12 Y4 (hiz), 13 A6 (in), 14 Y3 (hiz), 15 A7 (in), 16 Y2 (hiz), 17 A8 (in), 18 Y1 (hiz), 19 OE (in), 20 VCC (power)

## DM74S244N
designator U?
Octal 3-State Buffer/Line Driver/Line Receiver
footprint N20A (DIP, 20-Leads, Row Spacing 7.62mm, Pitch 2.54mm, Body 26.07x6.6mm)
3D model N20A (DIP, 20-Pin, Row Spacing 7.62 mm, Pitch 2.54 mm)
signal-integrity model DM74S244N
pins: 1 ~{OE}1 (in), 2 A1 (in), 3 Y8 (hiz), 4 A2 (in), 5 Y7 (hiz), 6 A3 (in), 7 Y6 (hiz), 8 A4 (in), 9 Y5 (hiz), 10 GND (power), 11 A5 (in), 12 Y4 (hiz), 13 A6 (in), 14 Y3 (hiz), 15 A7 (in), 16 Y2 (hiz), 17 A8 (in), 18 Y1 (hiz), 19 ~{OE}2 (in), 20 VCC (power)

## F100112DC
designator U?
Quad Driver; Note: All inputs have 50k Ohm pull-down resistors. VCC = VCCA = GND.
footprint 6Y (DIP, 24-Leads, Row Spacing 10.16mm, Pitch 2.54mm, Body 30.57x9.89mm)
3D model 6Y (DIP, 24-Pin, Row Spacing 10.16 mm, Pitch 2.54 mm)
pins: 1 ~{O}2D (oe), 2 ~{O}2C (oe), 3 ~{O}1C (oe), 4 O2C (oe), 5 O1C (oe), 6 VCC (power), 7 VCCA (power), 8 O1B (oe), 9 O2B (oe), 10 ~{O}1B (oe), 11 ~{O}2B (oe), 12 ~{O}2A (oe), 13 ~{O}1A (oe), 14 O2A (oe), 15 O1A (oe), 16 DA (in), 17 DB (in), 18 VEE (power), 19 EN (in), 20 DC (in), 21 DD (in), 22 O1D (oe), 23 O2D (oe), 24 ~{O}1D (oe)

## F100112FC
designator U?
Quad Driver; Note: All inputs have 50k Ohm pull-down resistors. VCC = VCCA = GND.
footprint 4V_N (CQFP, 24-Leads, Body 10x10mm; Pitch 1.27mm, Gullwing Leadform, IPC Medium Density)
footprint 4V_L (CQFP, 24-Leads, Body 10x10mm; Pitch 1.27mm, Gullwing Leadform, IPC High Density)
footprint 4V_M (CQFP, 24-Leads, Body 10x10mm; Pitch 1.27mm, Gullwing Leadform, IPC Low Density)
3D model F100112-4V (100-Pin Quad Cerpak 1.27 mm Pitch)
pins: 1 O1D (oe), 2 O2D (oe), 3 ~{O}1D (oe), 4 ~{O}2D (oe), 5 ~{O}2C (oe), 6 ~{O}1C (oe), 7 O2C (oe), 8 O1C (oe), 9 VCC (power), 10 VCCA (power), 11 O1B (oe), 12 O2B (oe), 13 ~{O}1B (oe), 14 ~{O}2B (oe), 15 ~{O}2A (oe), 16 ~{O}1A (oe), 17 O2A (oe), 18 O1A (oe), 19 DA (in), 20 DB (in), 21 VEE (power), 22 EN (in), 23 DC (in), 24 DD (in)

## F100123DC
designator U?
Hex Bus Driver; Note: All inputs have 50k Ohm pull-down resistors. VCC = VCCA = GND.
footprint 6Y (DIP, 24-Leads, Row Spacing 10.16mm, Pitch 2.54mm, Body 30.57x9.89mm)
3D model 6Y (DIP, 24-Pin, Row Spacing 10.16 mm, Pitch 2.54 mm)
pins: 1 VCCA (power), 2 O5 (oe), 3 VCCA (power), 4 O4 (oe), 5 VCCA (power), 6 VCC (power), 7 VCCA (power), 8 O1 (oe), 9 VCCA (power), 10 O2 (oe), 11 VCCA (power), 12 O3 (oe), 13 D3 (in), 14 D2 (in), 15 D1 (in), 16 DE1 (in), 17 DE2 (in), 18 VEE (power), 19 EN (in), 20 DE3 (in), 21 D6 (in), 22 D5 (in), 23 D4 (in), 24 O6 (oe)

## F100123FC
designator U?
Hex Bus Driver; Note: All inputs have 50k Ohm pull-down resistors. VCC = VCCA = GND.
footprint 4Q_N (CQFP, 24-Leads, Body 10x10mm; Pitch 1.27mm, Gullwing Leadform, IPC Medium Density)
footprint 4Q_L (CQFP, 24-Leads, Body 10x10mm; Pitch 1.27mm, Gullwing Leadform, IPC High Density)
footprint 4Q_M (CQFP, 24-Leads, Body 10x10mm; Pitch 1.27mm, Gullwing Leadform, IPC Low Density)
3D model F100123-4Q (100-Pin Quad Cerpak 1.27 mm Pitch)
pins: 1 D5 (in), 2 D4 (in), 3 O6 (oe), 4 VCCA (power), 5 O5 (oe), 6 VCCA (power), 7 O4 (oe), 8 VCCA (power), 9 VCC (power), 10 VCCA (power), 11 O1 (oe), 12 VCCA (power), 13 O2 (oe), 14 VCCA (power), 15 O3 (oe), 16 D3 (in), 17 D2 (in), 18 D1 (in), 19 DE1 (in), 20 DE2 (in), 21 VEE (power), 22 EN (in), 23 DE3 (in), 24 D6 (in)

## F100126DC
designator U?
9-Bit Backplane Driver; Note: All inputs have 50k Ohm pull-down resistors. VCC = VCCA = GND.
footprint 6Y (DIP, 24-Leads, Row Spacing 10.16mm, Pitch 2.54mm, Body 30.57x9.89mm)
3D model 6Y (DIP, 24-Pin, Row Spacing 10.16 mm, Pitch 2.54 mm)
pins: 1 VCCA (power), 2 O3 (oe), 3 O2 (oe), 4 O1 (oe), 5 O9 (oe), 6 VCC (power), 7 VCCA (power), 8 O8 (oe), 9 O7 (oe), 10 O6 (oe), 11 O5 (oe), 12 O4 (oe), 13 VCCA (power), 14 D4 (in), 15 D5 (in), 16 D6 (in), 17 D7 (in), 18 VEE (power), 19 VCCA (power), 20 D8 (in), 21 D9 (in), 22 D1 (in), 23 D2 (in), 24 D3 (in)

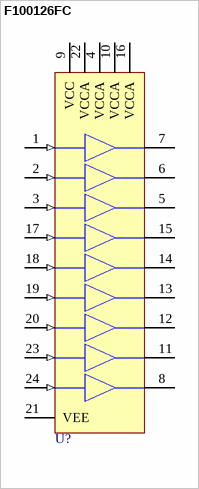
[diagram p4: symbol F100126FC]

## F100126FC
designator U?
9-Bit Backplane Driver; Note: All inputs have 50k Ohm pull-down resistors. VCC = VCCA = GND.
footprint 4V_N (CQFP, 24-Leads, Body 10x10mm; Pitch 1.27mm, Gullwing Leadform, IPC Medium Density)
footprint 4V_L (CQFP, 24-Leads, Body 10x10mm; Pitch 1.27mm, Gullwing Leadform, IPC High Density)
footprint 4V_M (CQFP, 24-Leads, Body 10x10mm; Pitch 1.27mm, Gullwing Leadform, IPC Low Density)
3D model F100126-4V (100-Pin Quad Cerpak 1.27 mm Pitch)
pins: 1 D1 (in), 2 D2 (in), 3 D3 (in), 4 VCCA (power), 5 O3 (oe), 6 O2 (oe), 7 O1 (oe), 8 O9 (oe), 9 VCC (power), 10 VCCA (power), 11 O8 (oe), 12 O7 (oe), 13 O6 (oe), 14 O5 (oe), 15 O4 (oe), 16 VCCA (power), 17 D4 (in), 18 D5 (in), 19 D6 (in), 20 D7 (in), 21 VEE (power), 22 VCCA (power), 23 D8 (in), 24 D9 (in)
